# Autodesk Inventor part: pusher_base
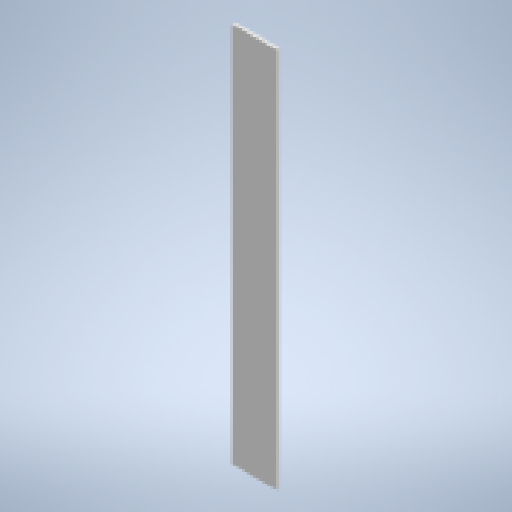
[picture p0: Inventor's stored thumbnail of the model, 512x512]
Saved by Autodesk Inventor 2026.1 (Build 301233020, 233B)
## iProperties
Created: 2026-10
Part Number: pusher_base
Material: Generic
Document SubType Name: Modeling
Designer: alolo
Density: 1 g/cm^3
Appearance: Default
Author: alolo
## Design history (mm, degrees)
sketch "Sketch1"
  geometry: L1 (0, 0)-(65, 0); L2 (65, 0)-(65, 300); L3 (65, 300)-(0, 300); L4 (0, 300)-(0, 0); L5 (0, 0)-(65, 0); L6 (65, 0)-(65, -300); L7 (65, -300)-(0, -300); L8 (0, -300)-(0, 0)
  constraints: 16 end point, 4 parallel, 2 horizontal, 2 perpendicular
  dimensions: "d0" = 65 distance of L3.end L2.end (= slide_width); "d1" = 300 distance of L2.end L1.end; "d4" = 300 distance of L5.end L6.end; "d5" = 65 distance of L6.end L7.end (= d0)
extrude "Extrusion1" new body sketch "Sketch1" distance "d2" = 5 (= wood_thickness); taper "d3" = 0 deg
body "Solid1"
other parameters: "slide_length" = 195 [user parameter], "slide_angle" = 7 deg [user parameter], "slide_width" = 65 [user parameter; used in 1 equation term], "wood_thickness" = 5 [user parameter; used in 1 equation term], "aclyric_thickness" = 6 [user parameter]
